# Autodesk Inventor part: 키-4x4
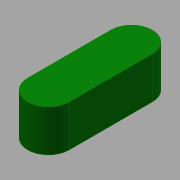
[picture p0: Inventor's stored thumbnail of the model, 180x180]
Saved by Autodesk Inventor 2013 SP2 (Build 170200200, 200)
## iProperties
Created: 2015-12
Part Number: 키-4x4
Document SubType Name: Modeling
Designer: mdu
Density: 7.86 g/cm^3
Material: 강철, 연강
Author: mdu
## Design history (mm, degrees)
sketch "스케치1"
  geometry: L1 (-2, -10)-(-2, -2) reference; L2 (2, -2)-(2, -10) reference; A1 r 2 centre (0, -2) between (2, -2) and (-2, -2) reference; A2 r 2 centre (0, -10) between (-2, -10) and (2, -10) reference; 1 further point
extrude "돌출1" new body sketch "스케치1" distance "d0" = 4; taper "d1" = 0 deg
node "솔리드1"
node "참조1"
